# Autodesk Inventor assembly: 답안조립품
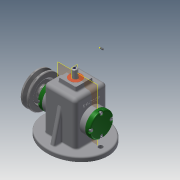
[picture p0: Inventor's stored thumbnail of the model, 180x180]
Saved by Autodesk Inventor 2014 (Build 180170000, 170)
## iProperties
Created: 2017-07
Part Number: 답안조립품
Document SubType Name: Assembly
Designer: user
Author: user
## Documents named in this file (16)
- C:\Users\user\Desktop\470708V1010\답안조립품.iam
- C:\Users\user\Desktop\470708V1010\V벨트풀리.ipt
- C:\Users\user\Desktop\470708V1010\고정핀 1.2 x  8.ipt
- C:\Users\user\Desktop\470708V1010\뒤커버.ipt
- C:\Users\user\Desktop\470708V1010\링크.ipt
- C:\Users\user\Desktop\470708V1010\멈춤나사 M3x8.ipt
- C:\Users\user\Desktop\470708V1010\베어링 12 x 32 x 10.ipt
- C:\Users\user\Desktop\470708V1010\본체.ipt
- C:\Users\user\Desktop\470708V1010\볼트 M4 x 12.ipt
- C:\Users\user\Desktop\470708V1010\부시.ipt
- C:\Users\user\Desktop\470708V1010\슬라이드.ipt
- C:\Users\user\Desktop\470708V1010\앞커버.ipt
- C:\Users\user\Desktop\470708V1010\오일실 12 25 7.ipt
- C:\Users\user\Desktop\470708V1010\키 4 x 4 x 10.ipt
- C:\Users\user\Desktop\470708V1010\편심축.ipt
- C:\Users\user\Desktop\470708V1010\핀 5 x 18.ipt
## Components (3 placed, 3 different names)
1. V벨트풀리:1
2. 고정핀 1.2 x  8:1
3. 핀 5 x 18:1
